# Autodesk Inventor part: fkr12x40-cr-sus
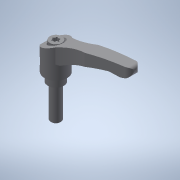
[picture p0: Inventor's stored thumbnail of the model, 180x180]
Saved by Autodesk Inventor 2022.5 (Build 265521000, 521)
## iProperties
Created: 2017-09
Part Number: fkr12x40-cr-sus
Material: 一般
Document SubType Name: Modeling
Designer: imaocorp
Density: 1 g/cm^3
Appearance: 既定
Author: imaocorp
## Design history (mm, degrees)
node "fkr12x40-cr-sus.x_t1"
node "fkr12x40-cr-sus"
node "Base1"
